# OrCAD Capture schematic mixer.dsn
size A; title: Mixer
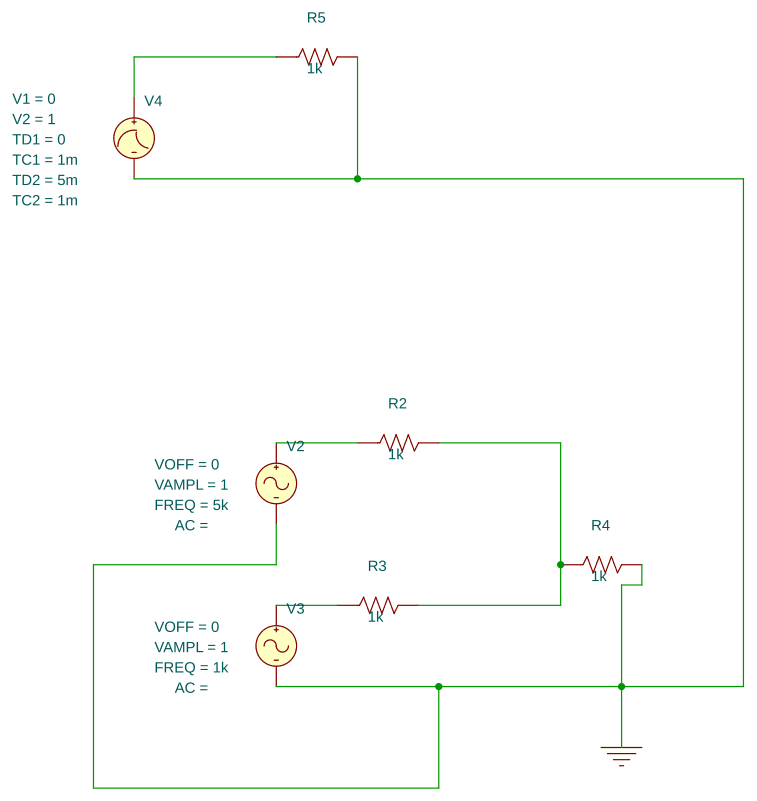
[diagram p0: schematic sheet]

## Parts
R2  1k  [AXRC05]
R3  1k  [AXRC05]
R4  1k  [AXRC05]
R5  1k  [AXRC05]
V2  VSIN
V3  VSIN
V4  VEXP

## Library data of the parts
R2-R5 = R
V2 = VSIN: FREQ: 5k; VAMPL: 1; VOFF: 0
V3 = VSIN: FREQ: 1k; VAMPL: 1; VOFF: 0
V4 = VEXP: TC1: 1m; TC2: 1m; TD1: 0; TD2: 5m; V1: 0; V2: 1

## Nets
0: R4.2 R5.2 V2.2(-) V3.2(-) V4.2(-)
N14680: R2.1 V2.1(+)
N14684: R2.2 R3.2 R4.1
N14691: R3.1 V3.1(+)
N15000: R5.1 V4.1(+)
